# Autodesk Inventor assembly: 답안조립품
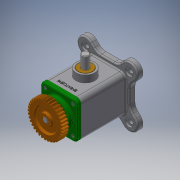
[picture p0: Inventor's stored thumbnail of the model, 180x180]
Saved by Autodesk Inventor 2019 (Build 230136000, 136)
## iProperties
Created: 2021-01
Part Number: 답안조립품
Material: 일반
Document SubType Name: Assembly
Designer: 3dpro21
Author: 3dpro21
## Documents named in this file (11)
- C:\Users\3dpro21\Desktop\710114V1001\답안조립품.iam
- C:\Users\3dpro21\Desktop\710114V1001\본체.ipt
- C:\Users\3dpro21\Desktop\710114V1001\베어링 6203.ipt
- C:\Users\3dpro21\Desktop\710114V1001\볼트 M4.ipt
- C:\Users\3dpro21\Desktop\710114V1001\부시.ipt
- C:\Users\3dpro21\Desktop\710114V1001\스퍼기어.ipt
- C:\Users\3dpro21\Desktop\710114V1001\슬라이더.ipt
- C:\Users\3dpro21\Desktop\710114V1001\오일 실.ipt
- C:\Users\3dpro21\Desktop\710114V1001\커버.ipt
- C:\Users\3dpro21\Desktop\710114V1001\키 4 x 4 x 14.ipt
- C:\Users\3dpro21\Desktop\710114V1001\편심축.ipt
